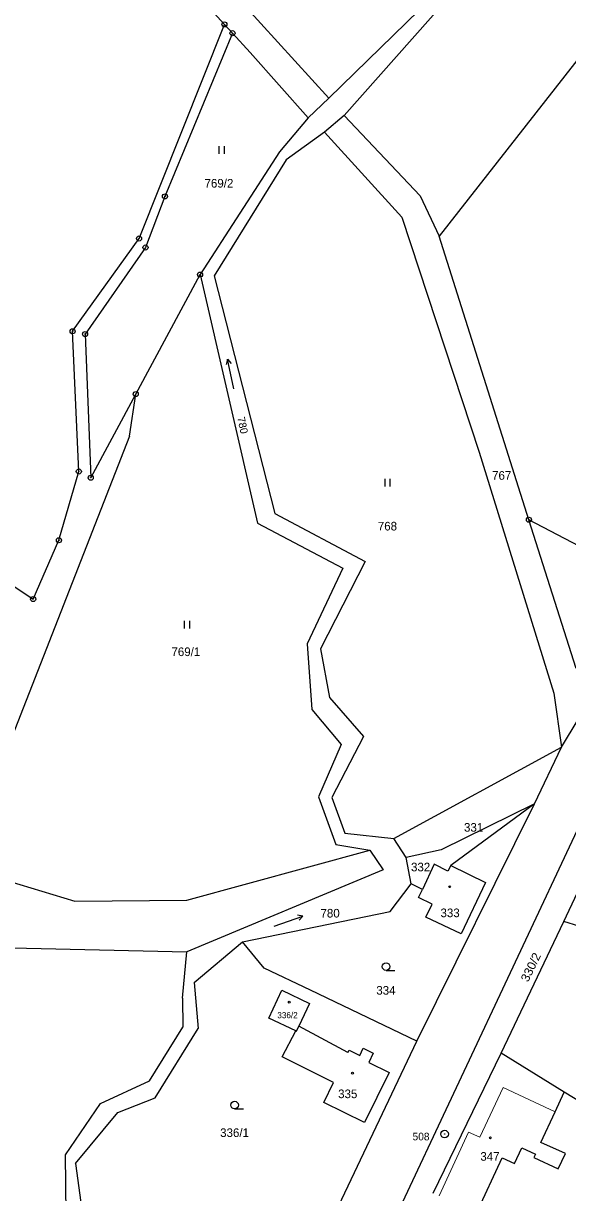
# Model space of a CAD drawing. Extents: x -727701 to -724405, y -960481 to -957284.
# Drawn here: x -727182.9 to -727075.6, y -958438.5 to -958207.9 of the extents above; entities that cross this region are included whole.
import ezdxf
from ezdxf.enums import TextEntityAlignment as Align

# ---------------------------------------------------------------- set-up
doc = ezdxf.new("R2010")
doc.units = 0
doc.header["$LTSCALE"] = 0.68
for name, color, linetype, lineweight in [('1', 7, 'Continuous', 25), ('3', 7, 'Continuous', 25), ('4', 7, 'Continuous', 13), ('5', 7, 'Continuous', 25), ('8', 7, 'Continuous', 25)]:
    doc.layers.add(name, color=color, linetype=linetype, lineweight=lineweight)
doc.layers.add('2', color=7, linetype='Continuous')

msp = doc.modelspace()

# ---------------------------------------------------------------- linework, layer by layer
at = {"layer": '1'}
for p, q in [((-727029.5, -958158.7), (-727100.91, -958249.86)), ((-727180.05, -958167.72), (-727143.26, -958208.09)), ((-727122.68, -958222.68), (-727098.83, -958199.36)), ((-727098.09, -958201.72), (-727119.62, -958226.1)), ((-727122.68, -958222.68), (-727139.44, -958204.22)), ((-727160.1, -958250.32), (-727143.26, -958208.09)), ((-727141.68, -958209.83), (-727154.99, -958242.03)), ((-727143.26, -958208.09), (-727141.68, -958209.83)), ((-727138.19, -958213.66), (-727141.68, -958209.83)), ((-727138.19, -958213.66), (-727126.75, -958226.52)), ((-727126.75, -958226.52), (-727122.68, -958222.68)), ((-727119.62, -958226.1), (-727123.53, -958229.38)), ((-727119.62, -958226.1), (-727104.66, -958241.89)), ((-727126.75, -958226.52), (-727132.39, -958233.21)), ((-727123.53, -958229.38), (-727131.11, -958234.83)), ((-727123.53, -958229.38), (-727108.29, -958246.12)), ((-727132.39, -958233.21), (-727148.07, -958257.44)), ((-727131.11, -958234.83), (-727145.32, -958257.71)), ((-727154.99, -958242.03), (-727158.84, -958252.1)), ((-727104.66, -958241.89), (-727100.91, -958249.86)), ((-727108.29, -958246.12), (-727093.03, -958292.48)), ((-727173.22, -958268.63), (-727160.1, -958250.32)), ((-727083.21, -958305.79), (-727100.91, -958249.86)), ((-727158.84, -958252.1), (-727170.76, -958269.16)), ((-727160.75, -958281), (-727148.07, -958257.44)), ((-727148.07, -958257.44), (-727136.72, -958306.46)), ((-727145.32, -958257.71), (-727133.32, -958304.55)), ((-727171.98, -958296.27), (-727173.22, -958268.63)), ((-727170.76, -958269.16), (-727169.64, -958297.51)), ((-727169.64, -958297.51), (-727160.75, -958281)), ((-727161.98, -958289.32), (-727160.75, -958281)), ((-727229.4, -958289.14), (-727180.99, -958321.43)), ((-727161.98, -958289.32), (-727195.24, -958374.24)), ((-727093.03, -958292.48), (-727078.31, -958339.97)), ((-727175.91, -958309.84), (-727171.98, -958296.27)), ((-727133.32, -958304.55), (-727115.52, -958314)), ((-727136.72, -958306.46), (-727119.93, -958315.33)), ((-727073.92, -958335.15), (-727083.21, -958305.79)), ((-727073.3, -958311.01), (-727083.21, -958305.79)), ((-727180.99, -958321.43), (-727175.91, -958309.84)), ((-727119.93, -958315.33), (-727126.96, -958330.29)), ((-727115.52, -958314), (-727124.32, -958331.27)), ((-727126.96, -958330.29), (-727126.01, -958343.21)), ((-727124.32, -958331.27), (-727122.52, -958340.87)), ((-727076.78, -958350.66), (-727068.18, -958336.28)), ((-727122.52, -958340.87), (-727115.82, -958348.54)), ((-727078.31, -958339.97), (-727076.78, -958350.66)), ((-727126.01, -958343.21), (-727120.23, -958350.12)), ((-727120.23, -958350.12), (-727124.73, -958360.46)), ((-727115.82, -958348.54), (-727122.05, -958360.54)), ((-727109.82, -958368.66), (-727076.78, -958350.66)), ((-727082.1, -958361.81), (-727076.78, -958350.66)), ((-727124.73, -958360.46), (-727121.32, -958369.85)), ((-727122.05, -958360.54), (-727119.55, -958367.59)), ((-727105.33, -958408.62), (-727082.1, -958361.81)), ((-727082.1, -958361.81), (-727100.54, -958370.91)), ((-727082.1, -958361.81), (-727098.64, -958373.95)), ((-727076.29, -958385), (-727065.92, -958362.84)), ((-727130.21, -958487.42), (-727073.19, -958365.95)), ((-727119.55, -958367.59), (-727109.82, -958368.66)), ((-727107.4, -958372.4), (-727109.82, -958368.66)), ((-727150.7, -958380.8), (-727114.56, -958370.97)), ((-727121.32, -958369.85), (-727114.56, -958370.97)), ((-727114.56, -958370.97), (-727111.98, -958374.82)), ((-727100.54, -958370.91), (-727107.4, -958372.4)), ((-727106.44, -958377.62), (-727107.4, -958372.4)), ((-727101.93, -958373.74), (-727104.2, -958378.68)), ((-727099.22, -958375.12), (-727101.93, -958373.74)), ((-727195.24, -958374.24), (-727172.8, -958381)), ((-727111.98, -958374.82), (-727150.67, -958391.02)), ((-727098.64, -958373.95), (-727099.22, -958375.12)), ((-727098.64, -958373.95), (-727091.8, -958377.35)), ((-727110.58, -958383.05), (-727106.44, -958377.62)), ((-727104.2, -958378.68), (-727106.44, -958377.62)), ((-727091.8, -958377.35), (-727096.6, -958387.48)), ((-727104.97, -958380.3), (-727104.2, -958378.68)), ((-727102.29, -958381.57), (-727104.97, -958380.3)), ((-727172.8, -958381), (-727150.7, -958380.8)), ((-727103.53, -958384.19), (-727102.29, -958381.57)), ((-727139.7, -958389), (-727110.58, -958383.05)), ((-727096.6, -958387.48), (-727103.53, -958384.19)), ((-727088.68, -958410.97), (-727076.29, -958385)), ((-727064.43, -958388.79), (-727076.29, -958385)), ((-727201.95, -958389.86), (-727150.67, -958391.02)), ((-727149.24, -958397.08), (-727139.7, -958389)), ((-727135.45, -958394.25), (-727139.7, -958389)), ((-727151.51, -958400.11), (-727150.67, -958391.02)), ((-727126.31, -958398.55), (-727135.45, -958394.25)), ((-727149.24, -958397.08), (-727148.42, -958406.1)), ((-727134.53, -958404.05), (-727131.95, -958398.58)), ((-727131.95, -958398.58), (-727126.47, -958401.16)), ((-727105.33, -958408.62), (-727126.31, -958398.55)), ((-727151.51, -958400.11), (-727151.47, -958405.84)), ((-727126.47, -958401.16), (-727128.58, -958405.63)), ((-727158.03, -958416.43), (-727151.47, -958405.84)), ((-727129.17, -958406.57), (-727134.53, -958404.05)), ((-727129.05, -958406.63), (-727128.58, -958405.63)), ((-727118.9, -958410.84), (-727128.58, -958405.63)), ((-727156.91, -958419.77), (-727148.42, -958406.1)), ((-727131.85, -958411.7), (-727129.17, -958406.57)), ((-727129.17, -958406.57), (-727129.05, -958406.63)), ((-727129.81, -958460.09), (-727105.33, -958408.62)), ((-727118.9, -958410.84), (-727118.69, -958410.39)), ((-727118.69, -958410.39), (-727116.56, -958411.43)), ((-727116.56, -958411.43), (-727115.87, -958410.02)), ((-727115.87, -958410.02), (-727113.9, -958410.98)), ((-727121.74, -958416.8), (-727131.85, -958411.7)), ((-727113.9, -958410.98), (-727114.81, -958412.84)), ((-727114.81, -958412.84), (-727110.78, -958414.81)), ((-727102.09, -958438.57), (-727088.68, -958410.97)), ((-727076.24, -958418.66), (-727088.68, -958410.97)), ((-727110.78, -958414.81), (-727115.61, -958424.68)), ((-727167.69, -958420.92), (-727158.03, -958416.43)), ((-727123.66, -958420.74), (-727121.74, -958416.8)), ((-727164.31, -958422.67), (-727156.91, -958419.77)), ((-727078.05, -958422.55), (-727076.24, -958418.66)), ((-727044.25, -958438.4), (-727076.24, -958418.66)), ((-727174.6, -958431.04), (-727167.69, -958420.92)), ((-727115.61, -958424.68), (-727123.66, -958420.74)), ((-727172.67, -958432.73), (-727164.31, -958422.67)), ((-727080.84, -958428.57), (-727078.05, -958422.55)), ((-727076.02, -958430.8), (-727080.84, -958428.57)), ((-727174.46, -958442.83), (-727174.6, -958431.04)), ((-727086.07, -958432.77), (-727084.61, -958429.63)), ((-727084.61, -958429.63), (-727081.91, -958430.88)), ((-727081.91, -958430.88), (-727082.23, -958431.58)), ((-727077.42, -958433.81), (-727076.02, -958430.8)), ((-727172.67, -958432.73), (-727171.59, -958440.46)), ((-727093.55, -958442.53), (-727088.5, -958431.65)), ((-727088.5, -958431.65), (-727086.07, -958432.77)), ((-727082.23, -958431.58), (-727077.42, -958433.81))]:
    msp.add_line(p, q, dxfattribs=at)
at = {"layer": '3'}
for p, q in [((-727144.281, -958233.64), (-727144.281, -958232.14)), ((-727143.28, -958233.64), (-727143.28, -958232.14)), ((-727142.639, -958274.097), (-727141.945, -958274.949)), ((-727111.561, -958299.22), (-727111.561, -958297.72)), ((-727110.56, -958299.22), (-727110.56, -958297.72)), ((-727151.121, -958327.23), (-727151.121, -958325.73)), ((-727150.12, -958327.23), (-727150.12, -958325.73)), ((-727127.794, -958383.956), (-727128.555, -958384.748)), ((-727111.393, -958394.67), (-727109.643, -958394.67)), ((-727141.253, -958421.97), (-727139.503, -958421.97))]:
    msp.add_line(p, q, dxfattribs=at)
for points in [[(-727141.391, -958279.966), (-727142.639, -958274.097), (-727142.926, -958275.157)], [(-727133.468, -958385.909), (-727127.794, -958383.956), (-727128.882, -958383.8)]]:
    msp.add_lwpolyline(points, dxfattribs=at)
for centre in [(-727111.3929, -958393.9198), (-727141.2529, -958421.2198)]:
    msp.add_circle(centre, 0.75, dxfattribs=at)
at = {"layer": '4'}
for p, q in [((-727092.9, -958427.58), (-727088.26, -958417.76)), ((-727088.26, -958417.76), (-727078.05, -958422.55)), ((-727100.93, -958439.11), (-727095.11, -958426.56)), ((-727095.11, -958426.56), (-727092.9, -958427.58))]:
    msp.add_line(p, q, dxfattribs=at)
at = {"layer": '5'}
for centre in [(-727098.8368, -958378.1692), (-727130.4868, -958400.9192), (-727117.9968, -958414.9192), (-727090.8168, -958427.6892)]:
    msp.add_circle(centre, 0.175, dxfattribs=at)
at = {"layer": '8'}
for centre, radius in [((-727143.26, -958208.0899), 0.5), ((-727143.26, -958208.0899), 0.0303), ((-727141.68, -958209.8299), 0.5), ((-727141.68, -958209.8299), 0.0303), ((-727154.99, -958242.0299), 0.5), ((-727154.99, -958242.0299), 0.0303), ((-727160.1, -958250.3199), 0.5), ((-727160.1, -958250.3199), 0.0303), ((-727158.84, -958252.0999), 0.5), ((-727158.84, -958252.0999), 0.0303), ((-727148.07, -958257.4399), 0.5), ((-727148.07, -958257.4399), 0.0303), ((-727173.22, -958268.6299), 0.5), ((-727173.22, -958268.6299), 0.0303), ((-727170.76, -958269.1599), 0.5), ((-727170.76, -958269.1599), 0.0303), ((-727160.75, -958280.9999), 0.5), ((-727160.75, -958280.9999), 0.0303), ((-727171.98, -958296.2699), 0.5), ((-727171.98, -958296.2699), 0.0303), ((-727169.64, -958297.5099), 0.5), ((-727169.64, -958297.5099), 0.0303), ((-727083.21, -958305.7899), 0.5), ((-727083.21, -958305.7899), 0.0303), ((-727175.91, -958309.8399), 0.5), ((-727175.91, -958309.8399), 0.0303), ((-727180.99, -958321.4299), 0.5), ((-727180.99, -958321.4299), 0.0303), ((-727099.84, -958426.9398), 0.75), ((-727099.84, -958426.9398), 0.03)]:
    msp.add_circle(centre, radius, dxfattribs=at)

# ---------------------------------------------------------------- texts
at = {"layer": '2'}
for s, height, p in [('769/2', 1.7, (-727147.19, -958240.285)), ('767', 1.7, (-727090.48, -958297.905)), ('768', 1.7, (-727113.01, -958307.905)), ('769/1', 1.7, (-727153.72, -958332.675)), ('331', 1.7, (-727096.01, -958367.305)), ('332', 1.7, (-727106.46, -958375.125)), ('780', 1.7, (-727124.32, -958384.235)), ('333', 1.7, (-727100.65, -958384.165)), ('334', 1.7, (-727113.31, -958399.445)), ('336/2', 1.2, (-727132.83, -958404.09)), ('335', 1.7, (-727120.84, -958419.855)), ('336/1', 1.7, (-727144.11, -958427.515)), ('347', 1.7, (-727092.79, -958432.195))]:
    msp.add_text(s, height=height, dxfattribs=at).set_placement(p)
msp.add_text('780', height=1.5, rotation=282, dxfattribs=at).set_placement((-727140.746, -958285.677))
at = {"layer": '2', "width": 1.05}
msp.add_text('330/2', height=1.7, rotation=64, dxfattribs=at).set_placement((-727082.0754, -958394.3966), align=Align.CENTER)
at = {"layer": '8'}
msp.add_text('508', height=1.5, dxfattribs=at).set_placement((-727106.16, -958428.175))

doc.saveas('drawing.dxf')
